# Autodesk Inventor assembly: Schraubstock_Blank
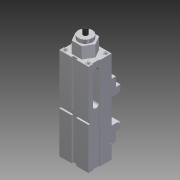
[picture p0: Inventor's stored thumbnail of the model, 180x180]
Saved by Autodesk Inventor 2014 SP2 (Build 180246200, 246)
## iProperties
Created: 2015-06
Part Number: Schraubstock_Blank
Document SubType Name: Assembly
Designer: e_krauts
Mass: 4334.15 g
Surface Area: 5057.15 cm^2
Volume: 4334.15 cm^3
Density: 1 g/cm^3
Sending System: SolidWorks 2011
Last Author: e_boekem
Author: e_krauts
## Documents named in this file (5)
- C:\SolidCAM_Temp\PRISMA IVCAM ZWISCHENSTAND1\Schraubstock_Blank.iam
- C:\SolidCAM_Temp\PRISMA IVCAM ZWISCHENSTAND1\Backe20x40.ipt
- C:\SolidCAM_Temp\PRISMA IVCAM ZWISCHENSTAND1\Unterteil.ipt
- C:\SolidCAM_Temp\PRISMA IVCAM ZWISCHENSTAND1\Backe 40 x 20 ohne.ipt
- C:\SolidCAM_Temp\PRISMA IVCAM ZWISCHENSTAND1\Spindel.ipt
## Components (4 placed, 4 different names)
1. Backe20x40:1 — Passend:2, Fluchtend:1
2. Unterteil:1 — Passend:1, Passend:2, Passend:4, Passend:5, Fluchtend:1
3. Backe 40 x 20 ohne:1 — Passend:3, Passend:4
4. Spindel:2 — Passend:1, Passend:3, Passend:5
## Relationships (6: Mate 5, Flush 1)
- Passend:1 [Mate]: Unterteil:1 ↔ Spindel:2
- Passend:2 [Mate]: Backe20x40:1 ↔ Unterteil:1
- Passend:3 [Mate]: Backe 40 x 20 ohne:1 ↔ Spindel:2
- Passend:4 [Mate]: Unterteil:1 ↔ Backe 40 x 20 ohne:1
- Passend:5 [Mate]: Unterteil:1 ↔ Spindel:2
- Fluchtend:1 [Flush]: Backe20x40:1 ↔ Unterteil:1
